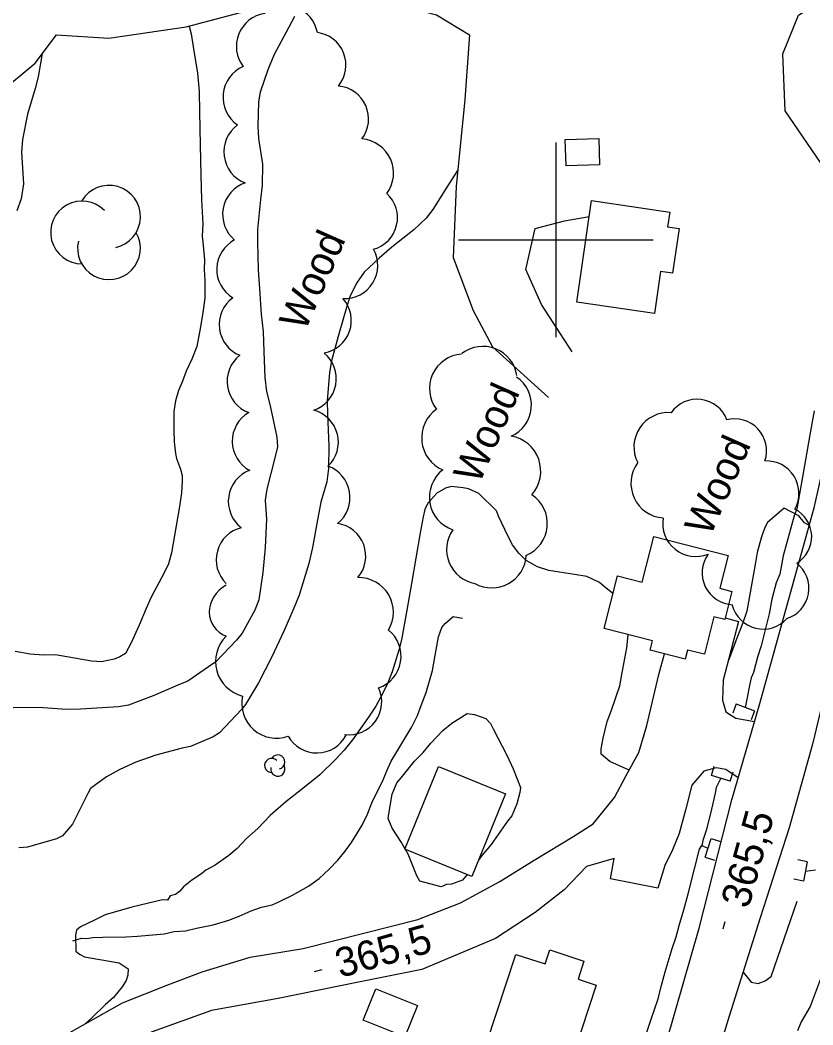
# Model space of a CAD drawing. Extents: x 287698 to 290158, y 5234163 to 5237182.
# Drawn here: x 289144.9 to 289226.4, y 5235319.3 to 5235422.6 of the extents above; entities that cross this region are included whole.
import ezdxf

# ---------------------------------------------------------------- set-up
doc = ezdxf.new("R2010")
doc.units = 0
for name, color, linetype in [('Niveau 1', 7, 'Continuous'), ('Niveau 19', 7, 'Continuous'), ('Niveau 2', 7, 'Continuous'), ('Niveau 21', 7, 'Continuous'), ('Niveau 26', 7, 'Continuous'), ('Niveau 3', 7, 'Continuous'), ('Niveau 31', 7, 'Continuous'), ('Niveau 4', 7, 'Continuous'), ('Niveau 44', 7, 'Continuous'), ('Niveau 61', 7, 'Continuous')]:
    doc.layers.add(name, color=color, linetype=linetype)

msp = doc.modelspace()

# ---------------------------------------------------------------- linework, layer by layer
at = {"layer": 'Niveau 1'}
msp.add_lwpolyline([(289173.13, 5235422.94), (289172.52, 5235421.79), (289171.06, 5235419.03), (289170.4, 5235417.47), (289169.63, 5235415.16), (289169.46, 5235414.18), (289169.36, 5235411.68), (289169.46, 5235410.41), (289169.85, 5235407.75), (289169.81, 5235405.56), (289169.66, 5235404.15), (289169.33, 5235401.05), (289169.34, 5235399.79), (289169.41, 5235396.92), (289169.55, 5235394.97), (289169.72, 5235392.36), (289169.93, 5235390.58), (289170, 5235388.47), (289170.11, 5235385.84), (289170.27, 5235384.39), (289170.63, 5235382.94), (289171.33, 5235379.72), (289171.38, 5235378.72), (289171.13, 5235377.6), (289170.3, 5235374.36), (289170.13, 5235373.25), (289170.25, 5235371.28), (289170.14, 5235368.39), (289169.9, 5235365.81), (289169.49, 5235362.99), (289169.06, 5235361.93), (289167.76, 5235359.56), (289167.19, 5235358.85), (289165.06, 5235356.64), (289164.3, 5235356.11), (289162.17, 5235354.63), (289161.38, 5235354.33), (289158.62, 5235353.15), (289156.08, 5235352.18), (289155.07, 5235351.99), (289151.16, 5235351.75), (289149.7, 5235351.73), (289146.85, 5235351.93), (289144.23, 5235351.91)], dxfattribs=at)
at = {"layer": 'Niveau 19'}
for points in [[(289154.07, 5235420.73), (289162.02, 5235421.87), (289169.42, 5235423.84), (289175.06, 5235424.58), (289181.88, 5235424.66), (289187.75, 5235423.11), (289191.12, 5235421.05), (289190.65, 5235414.41), (289189.74, 5235405.47), (289189.46, 5235398.17), (289191.5, 5235392.74), (289193.5, 5235389), (289199.24, 5235383.79)], [(289131.35, 5235411.91), (289131.43, 5235412.42), (289136.15, 5235412.1), (289139.6, 5235413.52), (289143.03, 5235415.27), (289146.49, 5235418.15), (289148.69, 5235421.07), (289154.07, 5235420.73)], [(289201.67, 5235388.49), (289198.53, 5235393.35), (289196.9, 5235396.94), (289197.88, 5235401.17), (289200.9, 5235401.93), (289203.44, 5235402.39)], [(289217.39, 5235361.14), (289218.76, 5235360.76), (289217.21, 5235354.73), (289217.11, 5235352.68), (289217.48, 5235351.48), (289218.49, 5235350.85), (289220.43, 5235350.51)], [(289203.84, 5235339.99), (289206.01, 5235342.7), (289207.21, 5235344.94), (289208.54, 5235347.31), (289209.34, 5235350.07), (289210.59, 5235355.33), (289211.17, 5235357.45)], [(289218.74, 5235344.72), (289217.48, 5235345.57), (289216.49, 5235345.74), (289215.19, 5235345.4), (289213.98, 5235343.95), (289213.37, 5235341.52), (289212.68, 5235339), (289212, 5235337.31), (289211.21, 5235335.71), (289210.47, 5235333.36)], [(289146.01, 5235317.4), (289148.4, 5235317.63), (289155.48, 5235321.6), (289160.11, 5235323.44), (289163.67, 5235324.76), (289168.6, 5235326.29), (289174.05, 5235327.16), (289180.26, 5235328.76), (289185.83, 5235330.16), (289190.21, 5235331.86), (289194.25, 5235334.05), (289197.77, 5235336.24), (289201.86, 5235338.72), (289203.84, 5235339.99)], [(289206, 5235336.43), (289203.14, 5235335.61), (289200.84, 5235333.2), (289197.88, 5235330.88), (289193.81, 5235328.2), (289186.22, 5235325.01), (289179.71, 5235323.7), (289171.46, 5235322.03), (289164.6, 5235320.8), (289158.5, 5235318.59), (289155.33, 5235316.16), (289152.88, 5235312.84), (289150.63, 5235310.35), (289150.01, 5235309.23), (289146.01, 5235317.4)], [(289210.47, 5235333.36), (289205.63, 5235334.32), (289206, 5235336.43)], [(289219.24, 5235324.74), (289220.08, 5235323.71), (289220.8, 5235323.58), (289221.52, 5235323.84), (289222.13, 5235324.29), (289224.81, 5235332.02)], [(289230.24, 5235331.59), (289228.33, 5235328.15), (289227.47, 5235324.78), (289226.14, 5235321.22), (289225.22, 5235319.62), (289224.84, 5235318.71)]]:
    msp.add_lwpolyline(points, dxfattribs=at)
at = {"layer": 'Niveau 2'}
for points in [[(289162.32, 5235421.95), (289162.51, 5235421.16), (289162.78, 5235419.61), (289163.19, 5235417.13), (289163.34, 5235415.24), (289163.38, 5235413.13), (289163.44, 5235409.76), (289163.52, 5235406.63), (289163.6, 5235404.11), (289163.73, 5235401.65), (289163.67, 5235400.37), (289163.73, 5235399.8), (289163.88, 5235397.94), (289163.86, 5235396.93), (289163.93, 5235395.84), (289163.92, 5235394.01), (289163.73, 5235392.52), (289163.48, 5235391.05), (289163.09, 5235389.03), (289162.61, 5235387.73), (289162.02, 5235386.51), (289161.65, 5235385.46), (289161.23, 5235384.51), (289160.92, 5235383.43), (289160.73, 5235382.35), (289160.74, 5235380.42)], [(289147.23, 5235419.13), (289146.8, 5235416.75), (289146.48, 5235415.55), (289145.72, 5235412.9), (289145.2, 5235410.29), (289145.1, 5235409.01), (289145.29, 5235405.75), (289145.07, 5235404.2), (289144.6, 5235402.96)], [(289189.91, 5235407.11), (289188.8, 5235405.39), (289187.35, 5235403.11), (289186.66, 5235402.23), (289185.41, 5235401.02), (289183.14, 5235399.24), (289181.85, 5235398.11), (289180.3, 5235396.68), (289179.53, 5235395.53), (289178.82, 5235394.12), (289178.48, 5235393.03), (289177.74, 5235390.43), (289176.94, 5235387.57), (289176.75, 5235386.35), (289176.49, 5235383.45), (289176.53, 5235382.09), (289176.68, 5235378.81), (289176.63, 5235376.49), (289176.46, 5235375.14), (289175.86, 5235373.02), (289175.51, 5235371.23), (289174.99, 5235368.38), (289174.6, 5235366.73), (289173.61, 5235363.49), (289173.09, 5235362.14), (289172.05, 5235359.78), (289170.8, 5235357.14), (289169.44, 5235354.46), (289168.12, 5235352.23), (289167.7, 5235351.72), (289165.43, 5235349.33), (289164.79, 5235348.92), (289162.47, 5235347.93), (289161.6, 5235347.75), (289158.88, 5235347.03), (289156.84, 5235346.3), (289155.19, 5235345.56), (289153.84, 5235344.8), (289152.19, 5235343.61), (289151.95, 5235343.18), (289150.33, 5235339.96), (289149.29, 5235338.73), (289148.7, 5235338.43), (289145.7, 5235337.59), (289144.81, 5235337.52)], [(289160.74, 5235380.42), (289160.79, 5235379.22), (289160.93, 5235378.03), (289161.03, 5235377.53), (289161.42, 5235376.41), (289161.59, 5235375.77), (289161.6, 5235375.15), (289161.52, 5235373.99), (289161.33, 5235372.6), (289160.98, 5235370.59), (289160.49, 5235367.82), (289160.21, 5235366.69), (289159.74, 5235365.77), (289158.43, 5235363.28), (289157.9, 5235362.1), (289157.19, 5235360.4), (289156.37, 5235358.59), (289155.77, 5235357.5), (289155.19, 5235357.13), (289154.61, 5235356.91), (289153.32, 5235356.61), (289152.27, 5235356.69), (289151.13, 5235356.89), (289148.57, 5235357.35), (289147.35, 5235357.32), (289145.98, 5235357.42), (289144.43, 5235357.69)], [(289193.9, 5235372.14), (289192.08, 5235373.93), (289191.03, 5235374.42), (289190.48, 5235374.52), (289189.25, 5235374.65), (289188.67, 5235374.47), (289187.78, 5235373.96), (289186.85, 5235372.92), (289186.55, 5235372.29), (289186.36, 5235371.51), (289186.07, 5235369.87), (289185.61, 5235367.27), (289185.15, 5235364.67), (289184.67, 5235361.94), (289184.13, 5235358.88), (289183.86, 5235357.83), (289183.17, 5235355.6), (289182.72, 5235354.46), (289182.15, 5235353.28), (289181.49, 5235352.08), (289180.74, 5235350.95), (289179.09, 5235348.62), (289178.23, 5235347.54), (289177.4, 5235346.61), (289175.75, 5235345.01), (289174, 5235343.61), (289172.24, 5235342.25), (289170.63, 5235340.83), (289169.36, 5235339.51), (289168.2, 5235338.46), (289167.25, 5235337.43), (289166.41, 5235336.72), (289165, 5235335.73), (289164.04, 5235335.23), (289163.6, 5235334.84), (289162.61, 5235334.18), (289161.74, 5235333.49), (289161.33, 5235333.03), (289160.91, 5235332.72), (289160.38, 5235332.57), (289160.08, 5235332.15), (289159.58, 5235332.16), (289156.42, 5235331.41)], [(289223.45, 5235372.42), (289221.76, 5235370.95), (289221.48, 5235370.43), (289221.13, 5235369.46), (289220.69, 5235367.87), (289220.5, 5235366.83), (289220.06, 5235364.33), (289219.62, 5235361.82), (289219.23, 5235360.63), (289218.59, 5235359.06), (289217.73, 5235356.76)], [(289226.03, 5235370.64), (289225.55, 5235370.9), (289224.97, 5235371.62), (289223.45, 5235372.42)], [(289205.82, 5235363.69), (289205.01, 5235364.34), (289204.48, 5235364.79), (289203.17, 5235365.39), (289201.9, 5235365.61), (289199.28, 5235366.02), (289198.11, 5235366.4), (289196.94, 5235367.05), (289196.2, 5235367.78), (289195.55, 5235368.64), (289195.08, 5235369.57), (289194.11, 5235371.59), (289193.9, 5235372.14)], [(289205.88, 5235363.67), (289205.82, 5235363.69)], [(289207.52, 5235345.49), (289205.56, 5235346.37), (289204.66, 5235347.14), (289204.67, 5235347.67), (289204.87, 5235348.77), (289205.28, 5235350.5), (289205.72, 5235351.66), (289206.59, 5235354.15), (289206.79, 5235355.31), (289207.28, 5235358.05), (289207.44, 5235359.41)], [(289184.49, 5235337.43), (289184.13, 5235338.05), (289183.17, 5235339.52), (289182.76, 5235340.52), (289182.83, 5235341.02), (289183.18, 5235343.03), (289183.65, 5235344.2), (289184.09, 5235344.71), (289185.47, 5235346.42), (289186.36, 5235347.32), (289187.15, 5235348.28), (289188.38, 5235349.58), (289189.3, 5235350.31), (289190.9, 5235351.33), (289191.65, 5235351.22), (289192.8, 5235350.8), (289193.28, 5235350.28), (289193.55, 5235349.75), (289194.96, 5235347.04), (289195.62, 5235345.63), (289196.36, 5235343.71), (289196.31, 5235343.21), (289196, 5235342.03), (289195.46, 5235340.8), (289195.04, 5235340.25), (289193.34, 5235337.86), (289192.41, 5235336.73), (289192.05, 5235336.26)], [(289188.2, 5235333.49), (289186.01, 5235334.08), (289185.7, 5235334.62), (289185.51, 5235335.16), (289184.83, 5235336.85), (289184.54, 5235337.34)], [(289190.87, 5235334.76), (289190.4, 5235334.2), (289189.27, 5235333.77), (289188.75, 5235333.74), (289188.2, 5235333.49)], [(289156.42, 5235331.41), (289153.68, 5235330.64), (289152.66, 5235330.11), (289151.15, 5235329.4), (289150.74, 5235329.05), (289150.63, 5235328.54), (289150.67, 5235326.91), (289151.06, 5235326.59), (289151.58, 5235326.3), (289152.13, 5235326.2), (289155.12, 5235325.68), (289156.04, 5235325.09), (289156.02, 5235324.44), (289155.86, 5235323.88), (289155.45, 5235323.24), (289154.56, 5235322.14), (289153.73, 5235321.43), (289152.25, 5235319.99), (289151.66, 5235319.46)]]:
    msp.add_lwpolyline(points, dxfattribs=at)
at = {"layer": 'Niveau 21'}
for points in [[(289220.96, 5235352.33), (289226.57, 5235372.6), (289230.44, 5235389.9), (289230.95, 5235400.07), (289227.65, 5235407.3), (289223.58, 5235413.24), (289223.33, 5235419.11), (289224.94, 5235423.08), (289229.29, 5235425.82), (289234.71, 5235426.34), (289239.78, 5235424.41), (289243.41, 5235420.3), (289243.79, 5235414.97), (289241.94, 5235407.82), (289239.36, 5235399), (289236.41, 5235389.25), (289232.61, 5235374.68), (289230.01, 5235363.33), (289226.38, 5235348.16)], [(289144.32, 5235289.83), (289156.39, 5235287.08), (289163.7, 5235285.24), (289172.81, 5235282.64), (289181.47, 5235280.28), (289186.29, 5235279.29), (289189.57, 5235278.69), (289192.73, 5235278.48), (289194.61, 5235278.94), (289196.2, 5235280.12), (289197.52, 5235281.71), (289200.34, 5235285.72), (289202.81, 5235291.18), (289205.07, 5235296.98), (289207.26, 5235303.19), (289210.59, 5235314.83), (289214.72, 5235329.25), (289218.08, 5235342.45), (289220.96, 5235352.33)], [(289226.38, 5235348.16), (289223.99, 5235339.58), (289221, 5235330.32), (289217.82, 5235320.23), (289214.91, 5235310.67), (289211.96, 5235300.96), (289209.46, 5235292.42), (289207.26, 5235286.74), (289205.17, 5235282.94), (289202.55, 5235277.74), (289200.56, 5235273.18), (289198.27, 5235266.47), (289196.66, 5235261.76), (289194.9, 5235256.26), (289193.78, 5235251.28), (289192.77, 5235244.98), (289192.22, 5235239.43), (289191.81, 5235234.33), (289191.98, 5235228.18), (289192.39, 5235221.16), (289193.28, 5235214.79), (289194.63, 5235206.23)]]:
    msp.add_lwpolyline(points, dxfattribs=at)
at = {"layer": 'Niveau 26'}
for p, q in [((289218.53, 5235352.3), (289218.19, 5235351.36)), ((289218.53, 5235352.3), (289220.43, 5235351.6)), ((289220.43, 5235351.6), (289220.08, 5235350.66)), ((289215.98, 5235344.95), (289216.27, 5235345.91)), ((289217.92, 5235344.37), (289215.98, 5235344.95)), ((289217.92, 5235344.37), (289218.21, 5235345.33)), ((289215.36, 5235336.56), (289215.97, 5235338.48)), ((289215.97, 5235338.48), (289216.92, 5235338.18)), ((289215.36, 5235336.56), (289216.31, 5235336.25)), ((289225.84, 5235336.08), (289224.86, 5235336.28)), ((289225.84, 5235336.08), (289225.44, 5235334.1)), ((289225.44, 5235334.1), (289224.46, 5235334.3))]:
    msp.add_line(p, q, dxfattribs=at)
at = {"layer": 'Niveau 3'}
for p, q in [((289217.18, 5235329.2), (289217.4, 5235329.96)), ((289175.19, 5235324.81), (289175.97, 5235325))]:
    msp.add_line(p, q, dxfattribs=at)
at = {"layer": 'Niveau 31'}
for points in [[(289204.48, 5235407.7), (289201.05, 5235407.6), (289200.97, 5235410.29), (289204.4, 5235410.39)], [(289202.15, 5235393.6), (289203.68, 5235404.02), (289211.71, 5235402.84), (289211.49, 5235401.33), (289212.66, 5235401.16), (289211.99, 5235396.58), (289210.77, 5235396.75), (289210.13, 5235392.42)], [(289217.7, 5235367.56), (289216.84, 5235364.18), (289218.08, 5235363.87), (289217.35, 5235360.97), (289216.25, 5235361.25), (289215.27, 5235357.4), (289213.54, 5235357.84), (289213.3, 5235356.91), (289209.68, 5235357.83), (289209.92, 5235358.78), (289204.96, 5235360.04), (289206.34, 5235365.46), (289208.88, 5235364.81), (289210.07, 5235369.49)], [(289194.83, 5235343.05), (289191.36, 5235334.56), (289184.47, 5235337.37), (289187.94, 5235345.86)], [(289204.14, 5235323.41), (289201.12, 5235314.23), (289199.17, 5235314.88), (289198.8, 5235313.74), (289193.67, 5235315.43), (289194.18, 5235316.97), (289192.88, 5235317.4), (289195.9, 5235326.57), (289198.9, 5235325.58), (289199.37, 5235327.02), (289202.89, 5235325.86), (289202.29, 5235324.01)], [(289184.48, 5235318.09), (289180.2, 5235319.81), (289181.49, 5235323.02), (289185.77, 5235321.3)]]:
    msp.add_lwpolyline(points, close=True, dxfattribs=at)
at = {"layer": 'Niveau 4'}
for points in [[(289226.55, 5235382.42), (289226.11, 5235379.96), (289225.66, 5235377.4), (289225.31, 5235375.43), (289224.75, 5235372.36), (289224.5, 5235371.64), (289224.12, 5235370.26), (289223.37, 5235367.53), (289223, 5235365.63), (289222.64, 5235364.76), (289222.2, 5235363.05), (289221.93, 5235361.55), (289221.57, 5235360.19), (289221.11, 5235358.28), (289220.72, 5235357.09), (289220.3, 5235355.54), (289220.06, 5235354.97), (289219.93, 5235354.37), (289219.63, 5235352.78), (289219.47, 5235351.95)], [(289150.35, 5235327.97), (289151.27, 5235328.23), (289151.81, 5235328.2), (289152.42, 5235328.29), (289153.46, 5235328.33), (289155.82, 5235328.36), (289157.02, 5235328.44), (289159.74, 5235328.69), (289160.79, 5235328.91), (289161.93, 5235328.99), (289163.07, 5235329.26), (289164.78, 5235329.61), (289166.4, 5235330.07), (289167.47, 5235330.49), (289168.69, 5235331.05), (289169.75, 5235331.41), (289170.85, 5235331.67), (289171.48, 5235331.94), (289172.95, 5235332.64), (289174.57, 5235333.57), (289175.69, 5235334.37), (289176.71, 5235335.32), (289177.61, 5235336.26), (289178.36, 5235337.17), (289179, 5235338.07), (289180.08, 5235339.83), (289180.63, 5235340.97), (289181.08, 5235342.13), (289181.56, 5235343.14), (289182.2, 5235344.33), (289182.62, 5235345.43), (289183.09, 5235346.42), (289183.67, 5235347.38), (289185.2, 5235349.95), (289185.79, 5235351.11), (289186.17, 5235352.14), (289186.66, 5235353.49), (289187.34, 5235355.73), (289187.54, 5235356.89), (289187.94, 5235359.18), (289188.28, 5235360.15), (289188.62, 5235360.58), (289189.45, 5235361.29), (289190, 5235361.19), (289190.4, 5235361.12)], [(289216.96, 5235344.66), (289216.49, 5235343.7), (289216.37, 5235343.14), (289215.98, 5235341.5), (289215.49, 5235339.39), (289215.12, 5235338.26), (289215, 5235337.77)], [(289208.06, 5235314.52), (289208.92, 5235317.21), (289209.76, 5235319.8), (289210.51, 5235321.99), (289210.82, 5235323.25), (289211.25, 5235324.76), (289211.95, 5235327.16), (289212.37, 5235328.36), (289212.66, 5235329.53), (289213.14, 5235331.13), (289213.58, 5235332.8), (289214.25, 5235335.36), (289214.75, 5235337.39), (289215, 5235337.77)], [(289215, 5235337.77), (289215.45, 5235337.55), (289215.66, 5235337.51)], [(289225.64, 5235335.1), (289226.68, 5235335.25)]]:
    msp.add_lwpolyline(points, dxfattribs=at)
at = {"layer": 'Niveau 44'}
for centre, radius, start, end in [((289169.24, 5235414.64), 3.44, 113.3484, 235.4009), ((289154.08, 5235402.36), 3.23, 282.2692, 149.7263), ((289151.31, 5235400.75), 3.23, 44.1154, 269.804), ((289154.08, 5235399.13), 3.23, 166.9369, 29.6212), ((289178.29, 5235397.36), 3.41, 267.3042, 29.1535), ((289189.8, 5235379.64), 3.59, 125.0069, 246.7238), ((289174.25, 5235379.2), 3.4, 313.3798, 75.1143), ((289211.28, 5235374.97), 3.57, 143.6122, 265.7461), ((289221.65, 5235373.94), 3.33, 330.8664, 92.7482), ((289223.12, 5235369.49), 3.17, 300.9495, 62.972), ((289214.37, 5235370.84), 3.39, 170.4103, 292.0587), ((289222.72, 5235364.19), 3.28, 288.263, 51.8357), ((289221.31, 5235363.27), 3.28, 194.2379, 317.9776), ((289180.64, 5235357.2), 3.45, 289.3999, 51.0806), ((289170.8, 5235345.98), 0.731, 44.1154, 269.804), ((289171.43, 5235346.34), 0.731, 282.2692, 149.7263), ((289171.43, 5235345.61), 0.731, 166.9369, 29.6212)]:
    msp.add_arc(centre, radius, start, end, dxfattribs=at)
for centre, major_axis, ratio, start_param, end_param in [((289172.21, 5235420.68), (0.13, 3.36), 0.992049, 4.931175, 7.022086), ((289170.49, 5235419.91), (-1.33, -3.1), 0.982534, 3.682828, 5.789397), ((289175.11, 5235417.94), (0.67, 3.3), 0.983581, 4.218834, 6.371967), ((289177.35, 5235412.4), (3.25, 1.03), 0.999678, 5.333192, 7.457782), ((289169.34, 5235409.04), (-3.45, 0.08), 0.99983, 5.372231, 7.500068), ((289179.79, 5235406.84), (3.27, 1.34), 0.997574, 5.259813, 7.383301), ((289169.18, 5235402.6), (-3.37, 0.61), 0.998561, 5.219483, 7.339025), ((289180.34, 5235402.27), (3.3, -0.77), 0.996966, 5.219052, 7.338499), ((289168.55, 5235396.95), (-3.32, 0.75), 0.999881, 5.409975, 7.534754), ((289168.81, 5235391.28), (-3.38, -0.42), 0.999859, 5.221052, 7.344532), ((289175.6, 5235391.7), (-0.66, 3.32), 0.999994, 3.119864, 5.244315), ((289192.51, 5235385.51), (-3.33, 1.18), 0.999871, 3.633725, 5.715645), ((289169.62, 5235385.44), (-3.36, -0.53), 0.999185, 5.21619, 7.345831), ((289174, 5235385.72), (3.37, -0.68), 0.99483, 5.241757, 7.362488), ((289190.56, 5235384.72), (-1.47, -3.22), 0.999769, 3.639385, 5.789984), ((289194, 5235383.01), (3.45, -0.54), 0.999017, 5.280872, 7.410652), ((289214.52, 5235380.32), (0.55, 3.24), 0.999976, 5.247959, 7.402364), ((289170.16, 5235379.3), (-3.41, -0.05), 0.999859, 5.223169, 7.3448), ((289211.56, 5235378.7), (-0.21, -3.53), 0.999995, 3.118909, 5.243456), ((289218.37, 5235378.31), (-2.25, 2.39), 0.999983, 3.635957, 5.788821), ((289194.78, 5235376.21), (3.65, 0.37), 0.999937, 5.462331, 7.584667), ((289175.43, 5235373.51), (3.37, 0.57), 0.999978, 5.222268, 7.344591), ((289190.54, 5235373.55), (0.58, -3.49), 0.999641, 3.632651, 5.792127), ((289169.75, 5235373.12), (-3.37, 0.5), 0.999977, 5.22213, 7.346959), ((289195.59, 5235370.84), (-2.43, 2.57), 0.999415, 2.785306, 4.9404), ((289168.42, 5235367.13), (-0.89, -3.26), 0.982446, 3.637669, 5.787109), ((289177.07, 5235367.49), (3.18, 1.2), 0.999796, 5.216227, 7.344358), ((289192.31, 5235368.17), (1.59, -3.16), 0.999768, 3.635979, 5.642908), ((289193.43, 5235367.77), (1.15, 3.35), 0.999795, 2.958259, 4.990694), ((289218.31, 5235365.78), (1.44, -2.95), 0.999983, 3.635498, 5.78928), ((289179.72, 5235361.71), (3.1, 1.8), 0.99816, 5.220468, 7.343881), ((289167.69, 5235362.03), (-3.12, -1.28), 0.866925, 4.860761, 7.017242), ((289168.83, 5235356.7), (-3.67, -1.03), 0.970658, 5.239532, 7.316103), ((289178.77, 5235352.47), (1.98, 2.73), 0.983634, 3.633409, 5.791369), ((289171.29, 5235352.35), (-2.35, -2.68), 0.999918, 5.217109, 7.345277), ((289175.44, 5235350.64), (3.38, 0.06), 0.999858, 3.634431, 5.790347)]:
    msp.add_ellipse(centre, major_axis=major_axis, ratio=ratio, start_param=start_param, end_param=end_param, dxfattribs=at)
at = {"layer": 'Niveau 61'}
for points in [[(289200, 5235410), (289200, 5235400), (289200, 5235390)], [(289190, 5235400), (289200, 5235400), (289210, 5235400)]]:
    msp.add_lwpolyline(points, dxfattribs=at)

# ---------------------------------------------------------------- texts
at = {"layer": 'Niveau 3'}
for rotation, p in [(74.5611, (289219.8, 5235331.17)), (15.7901, (289177.83, 5235324.13))]:
    msp.add_text('365,5', height=3, rotation=rotation, dxfattribs=at).set_placement(p)
at = {"layer": 'Niveau 44'}
for p in [(289174.21, 5235390.48), (289192.11, 5235374.77), (289215.86, 5235369.4)]:
    msp.add_text('Wood', height=3, rotation=66.1217, dxfattribs=at).set_placement(p)

doc.saveas('drawing.dxf')
